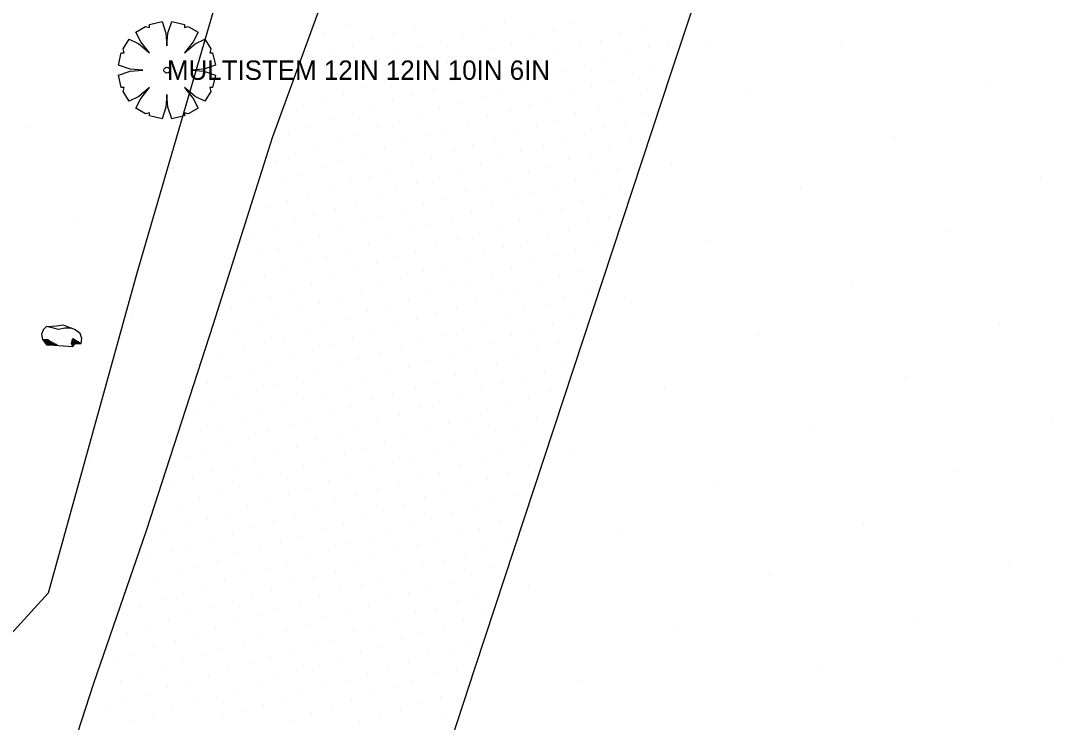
# Model space of a CAD drawing. Extents: x 1733582 to 1734070, y 467256 to 468256.
# Drawn here: x 1733938.7 to 1734035.4, y 468127.5 to 468192.6 of the extents above; entities that cross this region are included whole.
import ezdxf

# ---------------------------------------------------------------- set-up
doc = ezdxf.new("R2010")
doc.units = 0
for name, color, linetype in [('Default', 7, 'Continuous'), ('S_Ground_SpotElevation', 7, 'Continuous'), ('S_Property_RockBoulder', 7, 'Continuous'), ('S_Roadway_Edge_Pavement', 7, 'Continuous'), ('S_Text', 7, 'Continuous'), ('S_Trees_Bush_Line', 7, 'Continuous'), ('S_Trees_Decid_Pay', 7, 'Continuous')]:
    doc.layers.add(name, color=color, linetype=linetype)

# ---------------------------------------------------------------- blocks, each defined once
blk = doc.blocks.new('POINT_DISPLAY')
at = {"layer": 'Default'}
blk.add_line((0, 0), (0, 0), dxfattribs=at)

msp = doc.modelspace()

# ---------------------------------------------------------------- linework, layer by layer
at = {"layer": 'S_Property_RockBoulder'}
for p, q in [((1733943.503, 468163.135), (1733943.715, 468162.662)), ((1733943.503, 468163.135), (1733944.153, 468162.662)), ((1733943.503, 468163.135), (1733943.982, 468162.662)), ((1733943.503, 468163.135), (1733943.818, 468162.662)), ((1733943.503, 468163.135), (1733943.655, 468162.59)), ((1733943.503, 468163.135), (1733943.616, 468162.541)), ((1733943.503, 468163.135), (1733943.503, 468162.401)), ((1733940.82, 468163.039), (1733941.25, 468163.039)), ((1733940.853, 468163.08), (1733940.853, 468162.957)), ((1733940.901, 468162.95), (1733941.368, 468162.95)), ((1733940.949, 468163.073), (1733940.949, 468162.812)), ((1733940.991, 468162.834), (1733941.595, 468162.834)), ((1733941.052, 468162.717), (1733941.766, 468162.717)), ((1733941.066, 468163.073), (1733941.066, 468162.703)), ((1733941.142, 468162.607), (1733941.986, 468162.607)), ((1733941.189, 468163.073), (1733941.189, 468162.559)), ((1733941.301, 468162.985), (1733941.301, 468162.566)), ((1733941.396, 468162.874), (1733941.396, 468162.579)), ((1733941.505, 468162.854), (1733941.505, 468162.559)), ((1733941.623, 468162.764), (1733941.623, 468162.559)), ((1733941.725, 468162.73), (1733941.725, 468162.532)), ((1733941.876, 468162.675), (1733941.876, 468162.532)), ((1733942, 468162.614), (1733942, 468162.552)), ((1733943.399, 468162.662), (1733943.503, 468162.854)), ((1733943.399, 468162.662), (1733943.503, 468162.709)), ((1733943.399, 468162.662), (1733943.503, 468162.654)), ((1733943.399, 468162.662), (1733943.503, 468162.559))]:
    msp.add_line(p, q, dxfattribs=at)
for points in [[(1733941.34, 468162.559), (1733943.503, 468162.401), (1733943.715, 468162.662), (1733944.292, 468162.662), (1733944.347, 468163.135), (1733944.188, 468163.608), (1733943.715, 468163.924), (1733943.399, 468164.089), (1733942.767, 468164.089), (1733942.184, 468163.979), (1733941.711, 468164.089), (1733941.079, 468164.246), (1733940.765, 468163.924), (1733940.606, 468163.506), (1733940.71, 468163.032), (1733941.079, 468162.559), (1733941.34, 468162.559)], [(1733941.079, 468164.246), (1733942.027, 468164.295), (1733942.604, 468164.405), (1733943.399, 468164.089)], [(1733943.503, 468162.401), (1733943.399, 468162.662), (1733943.503, 468163.135), (1733944.292, 468162.662)]]:
    msp.add_lwpolyline(points, dxfattribs=at)
at = {"layer": 'S_Roadway_Edge_Pavement'}
for points in [[(1733939.159, 468111.651), (1733945.461, 468131.119), (1733950.37, 468145.312), (1733956.593, 468164.494), (1733962.063, 468181.811), (1733966.904, 468195.137), (1733973.025, 468213.342), (1733978.572, 468230.027), (1733983.551, 468244.93), (1733986.189, 468252.805)], [(1733958.83, 468065.658), (1733965.123, 468084.394), (1733980.896, 468132.58), (1733999.139, 468188), (1734013.932, 468232.458), (1734017.206, 468242.796)]]:
    msp.add_lwpolyline(points, dxfattribs=at)
at = {"layer": 'S_Trees_Bush_Line'}
msp.add_lwpolyline([(1733974.694, 468255.734), (1733949.472, 468169.202), (1733941.232, 468139.472), (1733936.458, 468134.269), (1733934.542, 468133.61), (1733930.759, 468135.587), (1733929.028, 468138.267), (1733930.579, 468153.395), (1733926.673, 468165.398), (1733915.501, 468177.757), (1733907.888, 468186.317)], dxfattribs=at)
at = {"layer": 'S_Trees_Decid_Pay'}
msp.add_lwpolyline([(1733950.001, 468188.056), (1733948.827, 468188.146), (1733947.744, 468188.507), (1733948.015, 468189.679), (1733948.286, 468189.679), (1733948.196, 468190.041), (1733948.737, 468190.943), (1733949.639, 468190.492), (1733950.632, 468189.679), (1733949.82, 468190.672), (1733949.369, 468191.575), (1733950.272, 468192.116), (1733950.632, 468192.026), (1733950.632, 468192.297), (1733951.805, 468192.567), (1733952.166, 468191.484), (1733952.256, 468190.312), (1733952.346, 468191.484), (1733952.707, 468192.567), (1733953.88, 468192.297), (1733953.88, 468192.026), (1733954.24, 468192.116), (1733955.143, 468191.575), (1733954.692, 468190.672), (1733953.88, 468189.679), (1733954.873, 468190.492), (1733955.775, 468190.943), (1733956.316, 468190.041), (1733956.226, 468189.679), (1733956.497, 468189.679), (1733956.768, 468188.507), (1733955.685, 468188.146), (1733954.511, 468188.056), (1733955.685, 468187.966), (1733956.768, 468187.604), (1733956.497, 468186.431), (1733956.226, 468186.431), (1733956.316, 468186.071), (1733955.775, 468185.169), (1733954.873, 468185.62), (1733953.88, 468186.431), (1733954.692, 468185.439), (1733955.143, 468184.537), (1733954.24, 468183.996), (1733953.88, 468184.086), (1733953.88, 468183.816), (1733952.707, 468183.545), (1733952.346, 468184.627), (1733952.256, 468185.801), (1733952.166, 468184.627), (1733951.805, 468183.545), (1733950.632, 468183.816), (1733950.632, 468184.086), (1733950.272, 468183.996), (1733949.369, 468184.537), (1733949.82, 468185.439), (1733950.632, 468186.431), (1733949.639, 468185.62), (1733948.737, 468185.169), (1733948.196, 468186.071), (1733948.286, 468186.431), (1733948.015, 468186.431), (1733947.744, 468187.604), (1733948.827, 468187.966), (1733950.001, 468188.056)], dxfattribs=at)
msp.add_circle((1733952.256, 468188.056), 0.283, dxfattribs=at)

# ---------------------------------------------------------------- block references
at = {"layer": 'S_Ground_SpotElevation'}
for p in [(1733956.672, 468192.521), (1733968.918, 468192.203), (1733983.62, 468192.549), (1733990, 468192.361), (1733996.296, 468192.226), (1733966.933, 468191.589), (1733973.3, 468191.534), (1733975.276, 468192.12), (1733979.67, 468191.377), (1733981.573, 468191.883), (1733988.124, 468191.667), (1733994.271, 468191.553), (1733969.502, 468190.303), (1733971.324, 468190.876), (1733975.876, 468190.221), (1733977.655, 468190.744), (1733984.299, 468190.493), (1733985.923, 468191.151), (1733990.633, 468190.334), (1733992.477, 468190.775), (1733996.952, 468190.206), (1733998.816, 468190.647), (1734002.721, 468190.73), (1734014.951, 468190.635), (1733967.551, 468189.679), (1733973.775, 468189.492), (1733980.162, 468189.298), (1733982.305, 468190.027), (1733988.545, 468189.872), (1733994.968, 468189.587), (1733965.785, 468189.095), (1733970.251, 468188.438), (1733972.041, 468189.039), (1733976.475, 468188.301), (1733978.272, 468188.834), (1733984.891, 468188.516), (1733986.759, 468189.083), (1733991.075, 468188.487), (1733992.994, 468189.114), (1733947.935, 468187.656), (1733968.137, 468187.784), (1733974.529, 468187.628), (1733980.772, 468187.556), (1733982.834, 468188.163), (1733987.126, 468187.407), (1733989.254, 468187.956), (1733995.509, 468187.791), (1733997.502, 468188.267), (1733966.27, 468187.261), (1733970.677, 468186.51), (1733972.488, 468187.038), (1733977.003, 468186.385), (1733978.843, 468186.961), (1733985.277, 468186.747), (1733991.721, 468186.594), (1733993.697, 468187.102), (1734028.553, 468186.763), (1733968.687, 468185.92), (1733975.056, 468185.747), (1733981.544, 468185.612), (1733983.418, 468186.257), (1733989.851, 468185.972), (1733996.196, 468185.832), (1734006.214, 468185.77), (1733964.891, 468184.73), (1733966.809, 468185.362), (1733971.249, 468184.623), (1733973.224, 468185.198), (1733977.596, 468184.454), (1733979.64, 468184.988), (1733985.917, 468184.895), (1733987.758, 468185.165), (1733992.342, 468184.701), (1733994.289, 468185.225), (1733967.443, 468183.464), (1733969.448, 468184.052), (1733975.796, 468183.866), (1733982.045, 468183.76), (1733984.118, 468184.244), (1733990.242, 468184.152), (1733996.727, 468184), (1733939.199, 468182.791), (1733965.541, 468182.772), (1733971.839, 468182.707), (1733973.82, 468183.307), (1733978.175, 468182.527), (1733980.142, 468182.894), (1733986.617, 468182.881), (1733988.542, 468183.417), (1733992.827, 468182.713), (1733994.801, 468183.154), (1733963.543, 468182.199), (1733968.189, 468181.505), (1733969.961, 468182.033), (1733976.358, 468181.985), (1733982.665, 468181.754), (1733984.668, 468182.4), (1733988.955, 468181.687), (1733991.062, 468182.041), (1734019.816, 468181.898), (1733966.037, 468180.863), (1733972.442, 468180.79), (1733974.273, 468181.318), (1733980.621, 468181.15), (1733987.193, 468181), (1733993.385, 468180.941), (1733995.277, 468181.446), (1733962.439, 468179.647), (1733964.187, 468180.272), (1733970.477, 468180.153), (1733976.833, 468179.986), (1733978.919, 468180.466), (1733983.239, 468179.875), (1733985.054, 468180.488), (1733989.55, 468179.784), (1733991.604, 468180.215), (1733952.8, 468178.919), (1733966.702, 468179.024), (1733968.504, 468179.552), (1733973.038, 468178.861), (1733974.976, 468179.501), (1733979.368, 468178.728), (1733981.349, 468179.342), (1733987.774, 468179.121), (1733994.089, 468178.934), (1733999.092, 468179.248), (1733962.862, 468177.836), (1733964.744, 468178.385), (1733969.272, 468177.677), (1733971.102, 468178.195), (1733977.566, 468178.124), (1733983.994, 468177.808), (1733985.836, 468178.54), (1733990.193, 468177.858), (1733992.125, 468178.399), (1734033.418, 468178.027), (1733967.333, 468177.059), (1733973.577, 468176.973), (1733975.417, 468177.509), (1733980.02, 468176.792), (1733981.953, 468177.341), (1733986.26, 468176.688), (1733988.332, 468177.028), (1733994.359, 468176.929), (1734011.079, 468177.033), (1733963.474, 468175.924), (1733965.356, 468176.509), (1733969.883, 468175.793), (1733971.799, 468176.407), (1733978.171, 468176.149), (1733984.415, 468176.109), (1733990.856, 468175.907), (1733992.763, 468176.377), (1733961.547, 468175.379), (1733967.873, 468175.211), (1733974.431, 468174.973), (1733976.102, 468175.643), (1733980.533, 468174.933), (1733982.389, 468175.493), (1733988.87, 468175.204), (1733944.064, 468174.054), (1733964.093, 468174), (1733965.878, 468174.576), (1733970.487, 468173.867), (1733972.217, 468174.461), (1733978.685, 468174.261), (1733985.043, 468174.189), (1733986.956, 468174.673), (1733991.314, 468173.997), (1733993.234, 468174.48), (1733962.13, 468173.376), (1733968.449, 468173.272), (1733974.931, 468173.146), (1733976.667, 468173.747), (1733981.257, 468172.867), (1733983.151, 468173.408), (1733989.546, 468173.248), (1734024.681, 468173.162), (1733960.294, 468172.784), (1733964.685, 468172.123), (1733966.465, 468172.675), (1733970.942, 468171.933), (1733972.795, 468172.424), (1733979.204, 468172.352), (1733985.752, 468172.18), (1733987.566, 468172.774), (1733992.036, 468171.95), (1734002.343, 468172.168), (1733960.839, 468170.942), (1733962.638, 468171.507), (1733969.029, 468171.361), (1733975.333, 468171.21), (1733977.278, 468171.742), (1733981.756, 468171.074), (1733983.556, 468171.623), (1733990.171, 468171.338), (1733965.268, 468170.229), (1733967.088, 468170.728), (1733971.679, 468170.075), (1733973.428, 468170.618), (1733979.946, 468170.491), (1733986.298, 468170.326), (1733988.264, 468170.8), (1733961.31, 468168.949), (1733963.387, 468169.595), (1733969.575, 468169.404), (1733976.052, 468169.316), (1733977.975, 468169.889), (1733982.458, 468169.068), (1733984.292, 468169.65), (1733990.754, 468169.485), (1733959.602, 468168.468), (1733965.719, 468168.235), (1733967.657, 468168.873), (1733972.25, 468168.164), (1733973.986, 468168.678), (1733978.488, 468167.961), (1733980.469, 468168.417), (1733986.896, 468168.176), (1733988.692, 468168.864), (1734015.944, 468168.297), (1733961.894, 468167.024), (1733963.861, 468167.702), (1733970.288, 468167.593), (1733976.656, 468167.41), (1733982.98, 468167.258), (1733984.941, 468167.695), (1733989.201, 468167.067), (1733991.313, 468167.653), (1733960.147, 468166.52), (1733966.437, 468166.338), (1733968.311, 468166.91), (1733972.693, 468166.243), (1733974.734, 468166.75), (1733981.032, 468166.536), (1733987.486, 468166.3), (1733994.737, 468166.966), (1733948.929, 468165.317), (1733958.221, 468165.906), (1733962.565, 468165.112), (1733964.677, 468165.77), (1733970.887, 468165.644), (1733977.209, 468165.528), (1733979.147, 468165.994), (1733983.662, 468165.27), (1733985.474, 468165.873), (1733989.968, 468165.163), (1733960.728, 468164.644), (1733967.012, 468164.492), (1733968.966, 468165.005), (1733973.514, 468164.22), (1733975.401, 468164.888), (1733981.689, 468164.733), (1733988.101, 468164.408), (1734029.546, 468164.425), (1733958.738, 468163.983), (1733963.064, 468163.129), (1733965.294, 468163.828), (1733969.447, 468163.161), (1733971.381, 468163.743), (1733977.882, 468163.534), (1733979.829, 468163.951), (1733984.212, 468163.419), (1733986.119, 468163.951), (1734007.208, 468163.432), (1733961.352, 468162.726), (1733967.72, 468162.573), (1733974.025, 468162.416), (1733975.895, 468162.906), (1733980.322, 468162.204), (1733982.265, 468162.673), (1733988.597, 468162.637), (1733957.438, 468161.457), (1733959.426, 468162.155), (1733963.845, 468161.416), (1733965.797, 468161.993), (1733970.042, 468161.205), (1733972.026, 468161.82), (1733978.542, 468161.564), (1733984.864, 468161.442), (1733986.691, 468162.106), (1733959.944, 468160.227), (1733961.72, 468160.731), (1733968.177, 468160.65), (1733974.659, 468160.456), (1733976.388, 468161.103), (1733982.856, 468160.784), (1733989.018, 468160.702), (1733958.027, 468159.603), (1733964.319, 468159.496), (1733966.148, 468159.988), (1733972.646, 468159.934), (1733979.073, 468159.736), (1733981.004, 468160.205), (1733985.39, 468159.554), (1733987.313, 468159.942), (1734020.809, 468159.56), (1733956.05, 468158.971), (1733960.588, 468158.288), (1733962.536, 468158.888), (1733968.838, 468158.769), (1733970.614, 468159.187), (1733975.309, 468158.484), (1733977.127, 468159.047), (1733981.502, 468158.411), (1733983.429, 468158.908), (1733998.471, 468158.567), (1733958.498, 468157.643), (1733964.93, 468157.549), (1733966.825, 468158.019), (1733971.243, 468157.437), (1733973.245, 468157.917), (1733979.615, 468157.825), (1733985.863, 468157.648), (1733987.883, 468158.246), (1733956.64, 468157.108), (1733962.966, 468156.931), (1733969.31, 468156.691), (1733975.781, 468156.691), (1733977.6, 468157.283), (1733982.065, 468156.553), (1733984.114, 468156.924), (1733955.022, 468156.342), (1733959.222, 468155.826), (1733960.991, 468156.276), (1733965.482, 468155.644), (1733967.418, 468156.253), (1733971.822, 468155.459), (1733973.831, 468156.017), (1733980.199, 468155.758), (1733986.56, 468155.664), (1734034.411, 468155.688), (1733955.407, 468154.608), (1733957.159, 468155.075), (1733961.627, 468154.455), (1733963.715, 468155.091), (1733969.961, 468154.939), (1733976.313, 468154.596), (1733978.392, 468155.256), (1733982.726, 468154.6), (1733984.661, 468155.079), (1734012.073, 468154.695), (1733959.827, 468153.888), (1733966.043, 468153.729), (1733968.061, 468154.311), (1733972.434, 468153.508), (1733974.393, 468154.161), (1733980.899, 468153.83), (1733955.876, 468152.687), (1733957.869, 468153.257), (1733962.443, 468152.538), (1733964.252, 468153.007), (1733970.659, 468152.889), (1733977.037, 468152.809), (1733978.852, 468153.4), (1733983.205, 468152.594), (1733985.289, 468153.204), (1733990.139, 468152.67), (1733945.057, 468151.715), (1733954.096, 468152.16), (1733960.398, 468151.999), (1733966.839, 468151.812), (1733968.73, 468152.435), (1733973.201, 468151.653), (1733974.943, 468152.053), (1733981.454, 468151.912), (1733956.525, 468150.736), (1733958.446, 468151.345), (1733962.845, 468150.587), (1733964.901, 468151.241), (1733971.292, 468150.907), (1733977.589, 468150.712), (1733979.507, 468151.422), (1733983.873, 468150.652), (1733985.854, 468151.338), (1734025.674, 468150.823), (1733954.581, 468150.203), (1733960.966, 468150.088), (1733967.253, 468149.935), (1733969.228, 468150.393), (1733973.799, 468149.725), (1733975.574, 468150.352), (1733980.036, 468149.593), (1733982.027, 468150.038), (1734003.336, 468149.83), (1733952.905, 468149.514), (1733956.996, 468148.794), (1733959.009, 468149.37), (1733963.499, 468148.722), (1733965.229, 468149.224), (1733971.772, 468149.174), (1733978.133, 468148.861), (1733984.557, 468148.679), (1733955.286, 468148.318), (1733961.671, 468148.044), (1733967.848, 468148.016), (1733969.745, 468148.568), (1733974.218, 468147.735), (1733976.134, 468148.472), (1733982.564, 468148.205), (1733953.253, 468147.635), (1733957.672, 468146.851), (1733959.713, 468147.535), (1733964.14, 468146.798), (1733965.916, 468147.393), (1733972.414, 468147.128), (1733978.678, 468147.004), (1733980.714, 468147.627), (1733954.012, 468145.83), (1733955.998, 468146.353), (1733962.128, 468146.27), (1733968.633, 468145.996), (1733970.385, 468146.606), (1733974.948, 468145.915), (1733976.851, 468146.423), (1733983.215, 468146.268), (1734016.938, 468145.958), (1733951.958, 468145.199), (1733958.352, 468145.014), (1733960.274, 468145.643), (1733964.504, 468144.786), (1733966.699, 468145.468), (1733972.931, 468145.336), (1733979.322, 468145.051), (1733981.281, 468145.522), (1733994.599, 468144.965), (1733954.438, 468143.891), (1733956.537, 468144.486), (1733962.789, 468144.289), (1733969.19, 468144.12), (1733971.118, 468144.543), (1733975.526, 468144.024), (1733977.333, 468144.615), (1733983.705, 468144.49), (1733952.696, 468143.314), (1733958.839, 468143.159), (1733960.858, 468143.774), (1733965.238, 468142.941), (1733967.287, 468143.469), (1733971.493, 468142.863), (1733973.518, 468143.434), (1733979.968, 468143.091), (1733981.848, 468143.663), (1733950.77, 468142.708), (1733955.112, 468141.946), (1733956.967, 468142.551), (1733963.328, 468142.352), (1733969.715, 468142.258), (1733975.964, 468142.043), (1733978.06, 468142.545), (1733982.3, 468141.916), (1734030.539, 468142.086), (1733953.282, 468141.276), (1733959.622, 468141.225), (1733961.469, 468141.812), (1733965.904, 468141.029), (1733967.923, 468141.464), (1733974.179, 468141.534), (1733980.55, 468141.202), (1734008.201, 468141.093), (1733951.194, 468140.658), (1733955.741, 468140.026), (1733957.595, 468140.623), (1733963.89, 468140.429), (1733970.356, 468140.286), (1733972.226, 468140.794), (1733976.715, 468140.017), (1733978.601, 468140.484), (1733985.862, 468140.1), (1733953.81, 468139.455), (1733960.151, 468139.35), (1733961.953, 468139.826), (1733966.445, 468139.171), (1733968.307, 468139.78), (1733972.813, 468139.023), (1733974.736, 468139.583), (1733981.163, 468139.278), (1733941.185, 468138.113), (1733949.842, 468138.125), (1733951.853, 468138.893), (1733956.293, 468138.154), (1733958.319, 468138.694), (1733962.548, 468138.016), (1733964.599, 468138.588), (1733971.003, 468138.321), (1733977.334, 468138.041), (1733979.222, 468138.826), (1733954.345, 468137.593), (1733960.76, 468137.395), (1733966.935, 468137.275), (1733968.921, 468137.856), (1733973.301, 468137.07), (1733975.326, 468137.665), (1733981.443, 468137.507), (1734021.803, 468137.221), (1733950.669, 468136.394), (1733952.411, 468137.007), (1733956.729, 468136.201), (1733958.819, 468136.833), (1733965.187, 468136.531), (1733971.558, 468136.464), (1733977.935, 468136.149), (1733979.808, 468136.938), (1733999.464, 468136.228), (1733948.604, 468135.817), (1733953.002, 468135.1), (1733955.022, 468135.592), (1733961.137, 468135.468), (1733963.355, 468135.93), (1733967.765, 468135.089), (1733969.602, 468135.932), (1733974.021, 468135.184), (1733975.926, 468135.751), (1733950.983, 468134.431), (1733957.335, 468134.284), (1733959.433, 468134.894), (1733965.848, 468134.68), (1733972.165, 468134.549), (1733978.502, 468134.288), (1733980.2, 468135), (1733947.253, 468133.182), (1733949.101, 468133.824), (1733955.563, 468133.737), (1733961.851, 468133.595), (1733963.877, 468134.077), (1733968.367, 468133.279), (1733970.207, 468133.996), (1733974.644, 468133.15), (1733976.47, 468133.91), (1734035.404, 468133.349), (1733951.788, 468132.522), (1733953.665, 468133.134), (1733957.922, 468132.364), (1733959.996, 468133.017), (1733964.316, 468132.288), (1733966.394, 468132.807), (1733972.716, 468132.694), (1733979.126, 468132.353), (1734013.066, 468132.356), (1733947.954, 468131.368), (1733949.742, 468131.826), (1733956.12, 468131.87), (1733962.38, 468131.596), (1733968.897, 468131.314), (1733970.871, 468131.938), (1733975.064, 468131.352), (1733977.117, 468131.98), (1733990.727, 468131.363), (1733952.311, 468130.695), (1733954.11, 468131.191), (1733958.684, 468130.495), (1733960.62, 468131.074), (1733964.863, 468130.239), (1733967.019, 468130.879), (1733973.345, 468130.763), (1733948.469, 468129.516), (1733950.379, 468130.102), (1733954.712, 468129.3), (1733956.858, 468129.823), (1733963.167, 468129.648), (1733969.38, 468129.546), (1733971.388, 468130.113), (1733975.88, 468129.294), (1733977.67, 468129.887), (1733946.583, 468128.851), (1733952.804, 468128.667), (1733959.241, 468128.612), (1733961.245, 468129.104), (1733965.713, 468128.368), (1733967.615, 468128.975), (1733973.901, 468128.658), (1733949.112, 468127.568), (1733950.992, 468128.192), (1733957.414, 468127.977), (1733963.754, 468127.624), (1733970.107, 468127.505), (1733971.964, 468128.218), (1733978.156, 468128.117)]:
    msp.add_blockref('POINT_DISPLAY', p, dxfattribs=at)

# ---------------------------------------------------------------- texts
at = {"layer": 'S_Text'}
msp.add_text('MULTISTEM 12IN 12IN 10IN 6IN', height=1.8, dxfattribs=at).set_placement((1733952.256, 468187.156))

doc.saveas('drawing.dxf')
